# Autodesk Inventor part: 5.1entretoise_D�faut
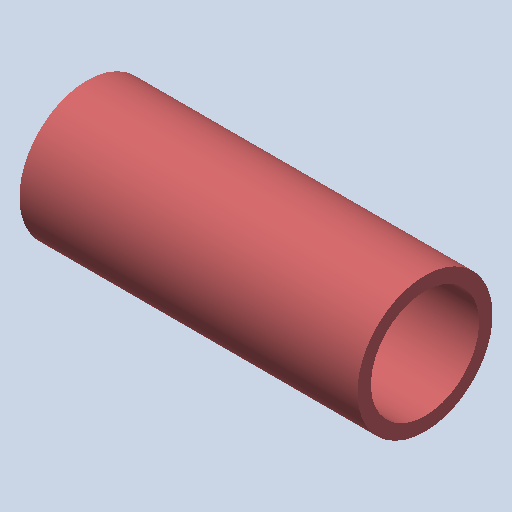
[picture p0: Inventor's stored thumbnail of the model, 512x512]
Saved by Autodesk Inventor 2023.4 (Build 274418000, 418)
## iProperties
Created: 2011-01
Part Number: 5.1entretoise_D�faut
Document SubType Name: Modeling
Designer: eric
Density: 1 g/cm^3
Mass: 0.706858 g
Surface Area: 14.7027 cm^2
Volume: 0.706858 cm^3
Material: Générique
Appearance: 255,128,128_1
Author: eric
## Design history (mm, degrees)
feature "Base1"
node "Corps solides"
node "Corps surfaciques"
node "Solide1"
